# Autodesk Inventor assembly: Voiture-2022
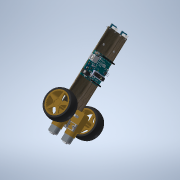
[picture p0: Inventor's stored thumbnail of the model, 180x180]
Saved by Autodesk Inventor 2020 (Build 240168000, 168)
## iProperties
Created: 2018-03
Part Number: Voiture-2022
Material: Générique
Document SubType Name: Assembly
Designer: Bruno
Author: Bruno
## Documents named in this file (12)
- C:\Users\bruno\Documents\1-Cours-2021-22\Maquettes-Inventor\Maquettes-Inventor-projets\Robot-2nde-Inventor\Voiture-2022.iam
- C:\Users\bruno\Documents\1-Cours-2021-22\Maquettes-Inventor\Maquettes-Inventor-projets\Robot-2nde-Inventor\Motoreducteur.iam
- C:\Users\bruno\Documents\1-Cours-2021-22\Maquettes-Inventor\Maquettes-Inventor-projets\Robot-2nde-Inventor\capteur.ipt
- C:\Users\bruno\Documents\1-Cours-2021-22\Maquettes-Inventor\Maquettes-Inventor-projets\Robot-2nde-Inventor\plaque.ipt
- C:\Users\bruno\Documents\1-Cours-2021-22\Maquettes-Inventor\Maquettes-Inventor-projets\Robot-2nde-Inventor\Roue.iam
- C:\Users\bruno\Documents\1-Cours-2021-22\Maquettes-Inventor\Maquettes-Inventor-projets\Robot-2nde-Inventor\Motoreducteur-gauche.iam
- C:\Users\bruno\Documents\1-Cours-2021-22\Maquettes-Inventor\Maquettes-Inventor-projets\Robot-2nde-Inventor\rotule.ipt
- C:\Users\bruno\Documents\1-Cours-2021-22\Maquettes-Inventor\Maquettes-Inventor-projets\Robot-2nde-Inventor\Arduino\Carte Arduino UNO.iam
- C:\Users\bruno\Documents\1-Cours-2021-22\Maquettes-Inventor\Maquettes-Inventor-projets\Robot-2nde-Inventor\vis-M2.4.ipt
- C:\Users\bruno\Documents\1-Cours-2021-22\Maquettes-Inventor\Maquettes-Inventor-projets\Robot-2nde-Inventor\ecrou-M2.8.ipt
- C:\Users\bruno\Documents\1-Cours-2021-22\Maquettes-Inventor\Maquettes-Inventor-projets\Robot-2nde-Inventor\vis-M1.4.ipt
- C:\Users\bruno\Documents\1-Cours-2021-22\Maquettes-Inventor\Maquettes-Inventor-projets\Robot-2nde-Inventor\ecrou-M1.8.ipt
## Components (30 placed, 11 different names)
1. Motoreducteur:1 [sub-assembly] — Placage:2, Affleurement:1, Placage:3, Affleurement:3, Logement:1, Affleurement:5
2. capteur:2 — Placage:6, Placage:13, Angle:1, Logement:21, Logement:22
3. plaque:1 — Placage:2, Affleurement:1, Placage:4, Affleurement:2, Placage:6, Placage:8, Placage:9, Placage:10, Affleurement:4, Placage:11, Placage:12, Affleurement:5, Logement:2, Logement:3, Logement:7, Logement:9, Logement:10, Logement:11, Logement:12, Logement:15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
4. Roue:1 [sub-assembly] — Placage:3, Placage:5
5. Roue:2 [sub-assembly] — Logement:1
6. Motoreducteur-gauche:1 [sub-assembly] — Placage:4, Affleurement:2, Affleurement:3, Placage:5, Logement:17, Logement:18
7. rotule:1 — Placage:8, Placage:9, Placage:10, Logement:8
8. Carte Arduino UNO:1 [sub-assembly] — Affleurement:4, Placage:11, Placage:12, Logement:4, Logement:5, Logement:6
9. vis-M2.4:1 — Logement:2
10. vis-M2.4:2 — Logement:3
11. vis-M2.4:3 — Logement:6
12. vis-M2.4:5 — Logement:5
13. vis-M2.4:6 — Logement:4
14. ecrou-M2.8:3 — Logement:7
15. ecrou-M2.8:4 — Logement:9
16. ecrou-M2.8:5 — Logement:10
17. ecrou-M2.8:6 — Logement:8
18. vis-M1.4:1 — Logement:12, Placage:13
19. vis-M1.4:2 — Logement:11, Placage:14
20. ecrou-M1.8:1 — Logement:22
21. ecrou-M1.8:2 — Logement:21
22. vis-M2.4:7 — Logement:15
23. vis-M2.4:9 — Logement:16
24. vis-M2.4:10 — Logement:17
25. vis-M2.4:11 — Logement:18
26. capteur:3 — Placage:14, Placage:15, Angle:2, Logement:23, Logement:24
27. vis-M1.4:3 — Logement:19
28. vis-M1.4:4 — Logement:20
29. ecrou-M1.8:3 — Logement:23
30. ecrou-M1.8:4 — Logement:24
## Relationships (42: Insert 22, Mate 13, Flush 5, Angle 2)
- Placage:2 [Mate]: Motoreducteur:1 ↔ plaque:1
- Affleurement:1 [Flush]: Motoreducteur:1 ↔ plaque:1
- Placage:3 [Mate]: Motoreducteur:1 ↔ Roue:1
- Placage:4 [Mate]: plaque:1 ↔ Motoreducteur-gauche:1
- Affleurement:2 [Flush]: plaque:1 ↔ Motoreducteur-gauche:1
- Affleurement:3 [Flush]: Motoreducteur:1 ↔ Motoreducteur-gauche:1
- Placage:5 [Mate]: Roue:1 ↔ Motoreducteur-gauche:1
- Logement:1 [Insert]: Motoreducteur:1 ↔ Roue:2
- Placage:6 [Mate]: capteur:2 ↔ plaque:1
- Placage:8 [Mate]: plaque:1 ↔ rotule:1
- Placage:9 [Mate]: plaque:1 ↔ rotule:1
- Placage:10 [Mate]: plaque:1 ↔ rotule:1
- Affleurement:4 [Flush]: plaque:1 ↔ Carte Arduino UNO:1
- Placage:11 [Mate]: plaque:1 ↔ Carte Arduino UNO:1
- Placage:12 [Mate]: plaque:1 ↔ Carte Arduino UNO:1
- Affleurement:5 [Flush]: Motoreducteur:1 ↔ plaque:1
- Logement:2 [Insert]: plaque:1 ↔ vis-M2.4:1
- Logement:3 [Insert]: plaque:1 ↔ vis-M2.4:2
- Logement:4 [Insert]: Carte Arduino UNO:1 ↔ vis-M2.4:6
- Logement:5 [Insert]: Carte Arduino UNO:1 ↔ vis-M2.4:5
- Logement:6 [Insert]: Carte Arduino UNO:1 ↔ vis-M2.4:3
- Logement:7 [Insert]: plaque:1 ↔ ecrou-M2.8:3
- Logement:8 [Insert]: rotule:1 ↔ ecrou-M2.8:6
- Logement:9 [Insert]: plaque:1 ↔ ecrou-M2.8:4
- Logement:10 [Insert]: plaque:1 ↔ ecrou-M2.8:5
- Logement:11 [Insert]: plaque:1 ↔ vis-M1.4:2
- Logement:12 [Insert]: plaque:1 ↔ vis-M1.4:1
- Logement:15 [Insert]: plaque:1 ↔ vis-M2.4:7
- Logement:16 [Insert]: plaque:1 ↔ vis-M2.4:9
- Logement:17 [Insert]: Motoreducteur-gauche:1 ↔ vis-M2.4:10
- Logement:18 [Insert]: Motoreducteur-gauche:1 ↔ vis-M2.4:11
- Placage:13 [Mate]: capteur:2 ↔ vis-M1.4:1
- Placage:14 [Mate]: vis-M1.4:2 ↔ capteur:3
- Placage:15 [Mate]: plaque:1 ↔ capteur:3
- Angle:1: capteur:2 ↔ plaque:1
- Angle:2: plaque:1 ↔ capteur:3
- Logement:19 [Insert]: plaque:1 ↔ vis-M1.4:3
- Logement:20 [Insert]: plaque:1 ↔ vis-M1.4:4
- Logement:21 [Insert]: capteur:2 ↔ ecrou-M1.8:2
- Logement:22 [Insert]: capteur:2 ↔ ecrou-M1.8:1
- Logement:23 [Insert]: capteur:3 ↔ ecrou-M1.8:3
- Logement:24 [Insert]: capteur:3 ↔ ecrou-M1.8:4
